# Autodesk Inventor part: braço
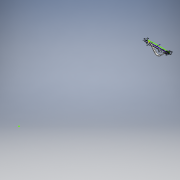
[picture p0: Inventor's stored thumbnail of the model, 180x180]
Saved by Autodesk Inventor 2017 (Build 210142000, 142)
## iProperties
Created: 2017-08
Part Number: braço
Material: Generic
Document SubType Name: Modeling
Designer: User
Density: 1 g/cm^3
Appearance: Default
Author: User
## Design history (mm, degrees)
sketch "Sketch1" dims "d51" = 24, "d53" = 24
  geometry: L1 (-40, 0)-(-40, -24.5); L2 (-80, 0)-(-80, -67.4); L3 (-120, 0)-(-120, -111); L4 (-160, 0)-(-160, -157.7); L5 (-200, 0)-(-200, -210.6); L6 (-240, 0)-(-240, -266); L7 (-280, 0)-(-280, -320); L8 (-320, 0)-(-320, -363); L9 (-360, 0)-(-360, -382); L10 (-400, 0)-(-400, -398.5); L11 (-440, 0)-(-440, -400); L12 (-480, 0)-(-480, -393); L13 (-560, 0)-(-560, -350); L14 (-600, 0)-(-600, -319); L15 (-640, 0)-(-640, -284); L16 (-680, 0)-(-680, -241); L17 (-720, 0)-(-720, -196); L18 (-760, 0)-(-760, -142); L19 (-800, 0)-(-800, -78); L20 (-843, 0)-(-864.355, -10.953); L21 (0, 0)-(0, -18.004); L22 (0, -15.887)-(-18, 0); L23 (-40, -24.5)-(-40, -59.727); L24 (-80, -67.4)-(-80, -102.716); L25 (-120, -111)-(-120, -147.25); L26 (-160, -157.7)-(-160, -196.822); L27 (-200, -210.6)-(-200, -251.513); L28 (-240, -266)-(-240, -306.915); L29 (-280, -320)-(-280, -357.34); L30 (-320, -363)-(-320, -392.788); L31 (-360, -382)-(-360, -413.164); L32 (-480, -393)-(-480, -418.067); L33 (-640, -284)-(-640, -316.804); L34 (-600, -319)-(-600, -349.593); L35 (-440, -400)-(-440, -424.889); L36 (-400, -398.5)-(-400, -423.326); L37 (-560, -350)-(-560, -379.681); L38 (-612.24, -310.973)-(-507.76, -389.027); A1 r 170.162 centre (-427.539, -231.127) between (-480, -393) and (-320, -363); A2 r 194.162 centre (-427.539, -231.127) between (-480, -418.067) and (-304.833, -381.6); A3 r 24 centre (-320, -363) between (-304.833, -381.6) and (-304.59, -381.399); A4 r 902.618 centre (-19.782, 373.107) between (-600.822, -317.625) and (-517.378, -379.965); A5 r 253.952 centre (-401.706, -151.419) between (-560, -350) and (-480, -393); A6 r 256.58 centre (-410.674, -171.03) between (-560, -379.681) and (-480, -418.067); A7 r 710.704 centre (-149.006, 200.134) between (-574.364, -369.227) and (-560, -379.681); 1 further point
  constraints: 76 end point, 23 vertical, 17 point on circle, 11 parallel, 7 centre point, 2 midpoint, 2 tangent, 1 point on line, 37 other
  dimensions: "d1" = 18 distance of L21.start L22.end; "d3" = 40 distance of L1.start L2.start; "d4" = 40 distance of L2.start L3.start; "d5" = 40 distance of L3.start L4.start; "d6" = 40 distance of L4.start L5.start; "d7" = 40 distance of L5.start L6.start; "d8" = 40 distance of L6.start L7.start; "d11" = 40 distance of L8.start L9.start; "d12" = 40 distance of L9.start L10.start; "d13" = 40 distance of L10.start L11.start; "d14" = 40 distance of L11.start L12.start; "d17" = 40 distance of L13.start L14.start; "d18" = 40 distance of L14.start L15.start; "d19" = 40 distance of L15.start L16.start; "d20" = 40 distance of L16.start L17.start; "d22" = 24.5 distance of L1.start L1.end; "d23" = 67.4 distance of L2.start L2.end; "d24" = 111 distance of L3.start L3.end; "d25" = 157.7 distance of L4.start L4.end; "d26" = 210.6 distance of L5.start L5.end; "d27" = 266 distance of L6.start L6.end; "d28" = 320 distance of L7.start L7.end; "d30" = 363 distance of L8.start L8.end; "d31" = 382 distance of L9.start L9.end; "d32" = 398.5 distance of L10.start L10.end; "d33" = 400 distance of L11.start L11.end; "d34" = 393 distance of L12.end L12.start; "d36" = 350 distance of L13.end L13.start; "d37" = 319 distance of L14.start L14.end; "d38" = 284 distance of L15.start L15.end; "d39" = 241 distance of L16.start L16.end; "d40" = 196 distance of L17.start L17.end; "d41" = 40 distance of L17.start L18.start; "d42" = 40 distance of L18.start L19.start; "d45" = 142 distance of L18.start L18.end; "d47" = 78 distance of L19.start L19.end; "d50" = 40 distance of L21.start L1.start; "d52" = 24 radial gap between concentric circles of A1 A2
extrude "Extrusion1" new body sketch "Sketch1" distance "d60" = 76; taper "d61" = 0 deg
sketch "Sketch2"
  geometry: L1 (400, 0)-(-165, 0); L2 (400, 0)-(1055, 0); L3 (320, 0)-(480, 0) reference; L4 (1055, 0)-(1055, 10); L5 (-165, 0)-(-165, 52); L6 (1055, 10)-(995, 10); L7 (995, 0)-(995, 55); L8 (400, 0)-(400, 196.062); A1 r 75 centre (986.029, -19.462) between (1055, 10) and (995, 55); A2 r 7469.095 centre (434.258, -7393.017) between (995, 55) and (-165, 52); 1 further point
  constraints: 14 end point, 4 point on circle, 4 vertical, 2 centre point, 2 horizontal, 1 collinear, 1 point on line
  dimensions: "d62" = 565 distance of L1.start L1.end; "d63" = 655 distance of L1.start L2.end; "d64" = 10 distance of L2.end L4.end; "d65" = 52 distance of L1.end L5.end; "d66" = 60 distance of L4.end L6.end; "d70" = 55 distance of L7.start L7.end; "d71" = 75 radius of A1
body "Solid1"
